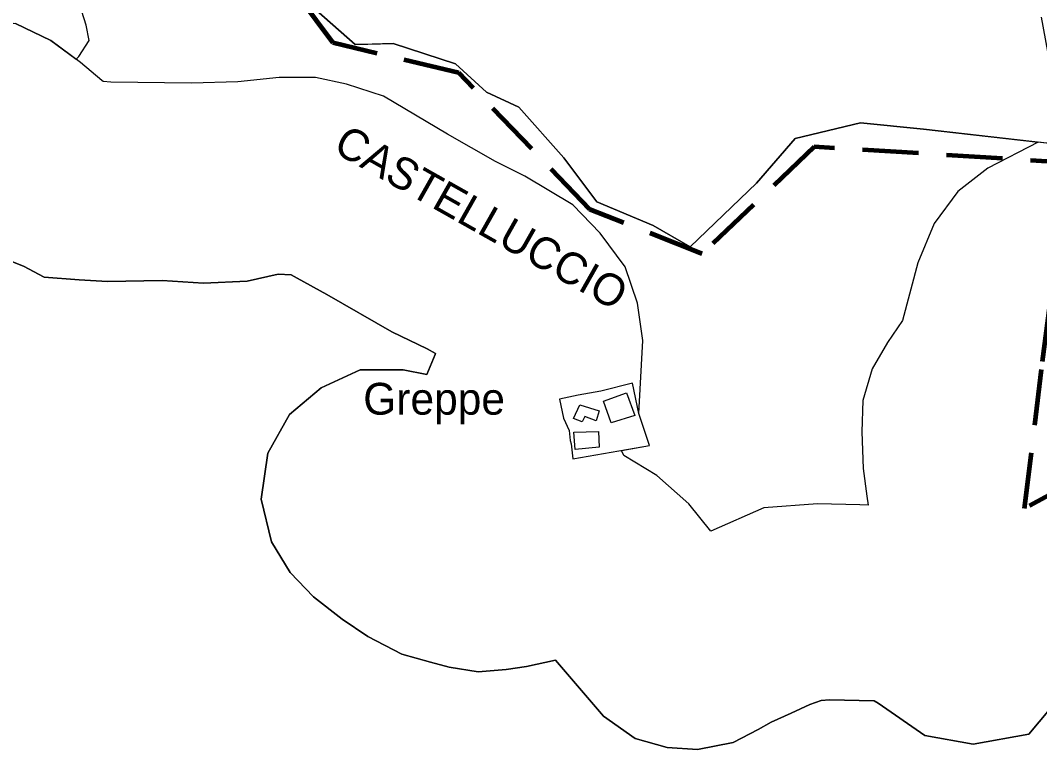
# Model space of a CAD drawing. Extents: x 645880 to 658994, y 884400 to 894744.
# Drawn here: x 657221 to 657766, y 890956 to 891347 of the extents above; entities that cross this region are included whole.
import ezdxf
from ezdxf.enums import TextEntityAlignment as Align

# ---------------------------------------------------------------- set-up
doc = ezdxf.new("R2010")
doc.units = 0
doc.header["$LTSCALE"] = 10
doc.linetypes.add('MEDIUM_DASHED', pattern=[4.5, 3, -1.5])
for name, color, linetype, lineweight in [('10', 7, 'Continuous', 25), ('15', 7, 'MEDIUM_DASHED', 100), ('16', 7, 'Continuous', 25), ('17', 7, 'Continuous', 25), ('18', 7, 'Continuous', 25), ('2', 7, 'Continuous', 25), ('55', 7, 'Continuous', 25)]:
    doc.layers.add(name, color=color, linetype=linetype, lineweight=lineweight)
doc.layers.add('60', color=7, linetype='Continuous')

msp = doc.modelspace()

# ---------------------------------------------------------------- linework, layer by layer
at = {"layer": '10'}
for points in [[(657400.09, 891334.33), (657379.16, 891352.71), (657364.34, 891378.02)], [(657767.03, 891348.96), (657770.45, 891330.62), (657796.14, 891285.04), (657790.22, 891279.18), (657704.19, 891289.09), (657670.46, 891292.46), (657635.51, 891284.06), (657614.74, 891260.2), (657579.26, 891226.05), (657559.49, 891237.53), (657529.31, 891250.16), (657511.7, 891273.75), (657487.58, 891300.87), (657470.34, 891308.9)], [(657470.34, 891308.9), (657453.84, 891324.08), (657420.34, 891334.9), (657403.53, 891334.4), (657400.09, 891334.33)]]:
    msp.add_lwpolyline(points, dxfattribs=at)
at = {"layer": '15'}
msp.add_lwpolyline([(657787.21, 890948.05), (657815.02, 890978.31), (657790.83, 891025.5), (657787.21, 891101.74), (657758.18, 891086.01), (657767.85, 891164.67), (657777.19, 891236.76), (657824.69, 891236.07), (657839.86, 891254.13), (657862.19, 891291.74), (657781.15, 891336.51), (657815.01, 891281.92), (657791.21, 891270.46), (657645.7, 891279.64), (657585.69, 891222.25), (657525.69, 891246.07), (657455.53, 891319.18), (657388.34, 891335.24), (657356.54, 891378.41)], dxfattribs=at)
at = {"layer": '16'}
for points in [[(657233.73, 891209.79), (657222.66, 891215.69), (657207.76, 891221.57), (657186.88, 891239.55), (657181.91, 891241.91)], [(657369.12, 891209.23), (657365.82, 891211.09), (657358.87, 891211.46), (657342.39, 891207.69), (657318.89, 891206.57), (657296.8, 891208.03), (657267.56, 891207.47)], [(657267.56, 891207.47), (657252.36, 891208.46), (657233.73, 891209.79)], [(657442.98, 891168.89), (657438.65, 891171.43), (657419.71, 891180.63), (657384.95, 891200.63), (657369.12, 891209.23)], [(657381.98, 891150.53), (657402.68, 891160.28), (657425.69, 891160.28), (657438.49, 891157.65), (657442.86, 891168.48), (657442.98, 891168.89)], [(657353.31, 891115.64), (657364.94, 891136.32), (657381.98, 891150.53)], [(657355.24, 891068.19), (657349.8, 891091.05), (657353.31, 891115.64)], [(657465.82, 890998.6), (657450.37, 891001.07), (657440.34, 891003.78), (657425.11, 891008.01), (657406.77, 891017.42), (657393.09, 891026.81), (657377.76, 891038.7), (657365.28, 891051.75), (657355.24, 891068.19)], [(657532.97, 890974.79), (657507.22, 891004.9), (657491.8, 891001.44), (657480.93, 890999.76), (657465.82, 890998.6)], [(657789.7, 891004.96), (657777.02, 890985.03), (657760.54, 890965.24), (657730.64, 890959.81), (657704.85, 890964.5)], [(657677.72, 890983.07), (657653.82, 890983.66), (657649.31, 890983.3), (657643.3, 890981.06), (657633.35, 890976.45)], [(657704.85, 890964.5), (657679.86, 890981.84), (657677.8, 890983.08), (657677.72, 890983.07)], [(657633.35, 890976.45), (657622.58, 890971.55), (657615.61, 890967.7), (657602.29, 890960.75), (657583.15, 890956.92), (657567, 890957.99), (657549.79, 890962.92), (657532.97, 890974.79)]]:
    msp.add_lwpolyline(points, dxfattribs=at)
at = {"layer": '17'}
for points in [[(657250.88, 891326.49), (657252.25, 891327.9), (657257.83, 891336.58), (657256.18, 891344.65), (657253.77, 891352.04), (657237.53, 891417.04), (657234.28, 891423.54), (657233.47, 891439.79)], [(656932.1, 891401.4), (656948.8, 891405.66), (656966.63, 891408.32), (656979.51, 891409.14), (656995.73, 891411.78), (657026.54, 891408.63), (657046.03, 891397.59), (657048.71, 891395.74), (657056.19, 891398.66), (657073.11, 891404.08), (657086.2, 891407.44), (657105.68, 891410.91), (657137.14, 891410.14), (657161.32, 891393.45), (657175.26, 891379.51), (657195.63, 891354.74), (657199.58, 891349.58), (657200.27, 891349.15), (657204.3, 891347.59), (657218.39, 891345.62), (657237.24, 891336.54), (657250.88, 891326.49)]]:
    msp.add_lwpolyline(points, dxfattribs=at)
at = {"layer": '18'}
for points in [[(657250.88, 891326.49), (657252.25, 891327.9), (657257.83, 891336.58), (657256.18, 891344.65), (657253.77, 891352.04), (657237.53, 891417.04), (657234.28, 891423.54), (657233.47, 891439.79)], [(657379.16, 891352.71), (657400.09, 891334.33), (657420.34, 891334.9), (657453.84, 891324.08), (657470.34, 891308.9), (657487.58, 891300.87), (657511.7, 891273.75), (657529.31, 891250.16), (657559.49, 891237.53), (657579.26, 891226.05), (657614.74, 891260.2), (657635.51, 891284.06), (657670.46, 891292.46), (657704.19, 891289.09), (657765.49, 891282.03)], [(657551.79, 891136.87), (657553.99, 891175.96), (657551.06, 891195.93), (657544.57, 891215.41), (657531.09, 891233.39), (657516.46, 891248.55), (657490.87, 891263.91), (657475.13, 891271.79), (657449.41, 891286.38), (657415.25, 891306.69), (657395.5, 891313.13), (657378.78, 891316.79), (657359.49, 891316.79), (657337.36, 891314.45), (657312.44, 891313.7), (657269.31, 891314.23), (657265.33, 891314.5), (657264.48, 891315.09), (657253.17, 891324.8), (657250.88, 891326.49)], [(657765.49, 891282.03), (657738.62, 891268.14), (657722.46, 891255.7), (657709.84, 891238.62), (657701.17, 891217.56), (657692.81, 891186.72)], [(657692.81, 891186.72), (657684.94, 891174.92), (657676.58, 891160.79), (657671.61, 891143.89), (657671.07, 891127.08), (657671.79, 891107.41), (657673.8, 891092.6), (657674.45, 891087.82), (657670.08, 891087.93), (657647.5, 891088.57), (657618.68, 891086.27), (657590.37, 891073.83), (657578.52, 891088.57), (657561.48, 891103.72), (657543.87, 891114.29), (657542.47, 891117.09)], [(657542.47, 891117.09), (657557.59, 891119.67), (657551.79, 891136.87)]]:
    msp.add_lwpolyline(points, dxfattribs=at)
at = {"layer": '2'}
for points in [[(657509.37, 891144.45), (657511.49, 891134.27), (657514.49, 891127.67), (657515.09, 891122.47), (657515.59, 891120.67), (657516.49, 891112.67), (657557.59, 891119.67), (657551.79, 891136.87), (657548.36, 891153.07), (657531.48, 891148.85), (657519.33, 891146.65)], [(657532.86, 891143.54), (657545.16, 891148), (657549.71, 891135.84), (657537, 891131.91)], [(657516.97, 891134.15), (657520.18, 891141.58), (657530.64, 891138.2), (657528.95, 891132.97), (657522.88, 891135.16), (657521.53, 891132.46)], [(657517.11, 891126.82), (657530.3, 891127.22), (657530.64, 891118.78), (657517.74, 891117.58)]]:
    msp.add_lwpolyline(points, close=True, dxfattribs=at)
at = {"layer": '55'}
for points in [[(657692.81, 891186.72), (657684.94, 891174.92), (657676.58, 891160.79), (657671.61, 891143.89), (657671.07, 891127.08), (657671.79, 891107.41), (657673.8, 891092.6), (657674.45, 891087.82), (657670.08, 891087.93), (657647.5, 891088.57), (657618.68, 891086.27), (657590.37, 891073.83), (657578.52, 891088.57), (657561.48, 891103.72), (657543.87, 891114.29), (657542.47, 891117.09), (657557.59, 891119.67), (657551.79, 891136.87), (657553.99, 891175.96), (657551.06, 891195.93), (657544.57, 891215.41), (657531.09, 891233.39), (657516.46, 891248.55), (657490.87, 891263.91), (657475.13, 891271.79), (657449.41, 891286.38), (657415.25, 891306.69), (657395.5, 891313.13), (657378.78, 891316.79), (657359.49, 891316.79), (657337.36, 891314.45), (657312.44, 891313.7), (657269.31, 891314.23), (657265.33, 891314.5), (657264.48, 891315.09), (657253.17, 891324.8), (657237.24, 891336.54), (657218.39, 891345.62)], [(656930.24, 891287.48), (656953.29, 891297.23), (656966.64, 891299.86), (656992.46, 891303.12), (657001.83, 891294.78), (657023.56, 891283.07), (657051.82, 891285.25), (657068.13, 891290.82), (657086.94, 891296.9), (657094.05, 891299.59), (657102.96, 891297.11), (657118.93, 891278.3), (657137.16, 891262.09), (657153.75, 891249.64), (657177.1, 891242.56), (657181.91, 891241.91), (657186.88, 891239.55), (657207.76, 891221.57), (657222.66, 891215.69), (657233.73, 891209.79)], [(657803.36, 891278.69), (657796.14, 891285.04), (657790.22, 891279.18), (657765.49, 891282.03), (657738.62, 891268.14), (657722.46, 891255.7), (657709.84, 891238.62), (657701.17, 891217.56), (657692.81, 891186.72)], [(657358.87, 891211.46), (657342.39, 891207.69), (657318.89, 891206.57), (657296.8, 891208.03), (657267.56, 891207.47), (657252.36, 891208.46), (657233.73, 891209.79), (657222.66, 891215.69), (657207.76, 891221.57)], [(657233.73, 891209.79), (657252.36, 891208.46), (657267.56, 891207.47), (657296.8, 891208.03), (657318.89, 891206.57), (657342.39, 891207.69), (657358.87, 891211.46)], [(657777.02, 890985.03), (657760.54, 890965.24), (657730.64, 890959.81), (657704.85, 890964.5), (657679.86, 890981.84), (657677.8, 890983.08), (657677.72, 890983.07), (657653.82, 890983.66), (657649.31, 890983.3), (657643.3, 890981.06), (657633.35, 890976.45), (657622.58, 890971.55), (657615.61, 890967.7), (657602.29, 890960.75), (657583.15, 890956.92), (657567, 890957.99), (657549.79, 890962.92), (657532.97, 890974.79), (657507.22, 891004.9), (657491.8, 891001.44), (657480.93, 890999.76), (657465.82, 890998.6), (657450.37, 891001.07), (657440.34, 891003.78), (657425.11, 891008.01), (657406.77, 891017.42), (657393.09, 891026.81), (657377.76, 891038.7), (657365.28, 891051.75), (657355.24, 891068.19), (657349.8, 891091.05), (657353.31, 891115.64), (657364.94, 891136.32), (657381.98, 891150.53), (657402.68, 891160.28), (657425.69, 891160.28), (657438.49, 891157.65), (657442.86, 891168.48), (657442.98, 891168.89), (657438.65, 891171.43), (657419.71, 891180.63), (657384.95, 891200.63), (657369.12, 891209.23), (657365.82, 891211.09), (657358.87, 891211.46)], [(657358.87, 891211.46), (657365.82, 891211.09), (657369.12, 891209.23), (657384.95, 891200.63), (657419.71, 891180.63), (657438.65, 891171.43), (657442.98, 891168.89), (657442.86, 891168.48), (657438.49, 891157.65), (657425.69, 891160.28), (657402.68, 891160.28), (657381.98, 891150.53), (657364.94, 891136.32), (657353.31, 891115.64), (657349.8, 891091.05), (657355.24, 891068.19), (657365.28, 891051.75), (657377.76, 891038.7), (657393.09, 891026.81), (657406.77, 891017.42), (657425.11, 891008.01), (657440.34, 891003.78), (657450.37, 891001.07), (657465.82, 890998.6), (657480.93, 890999.76), (657491.8, 891001.44), (657507.22, 891004.9), (657532.97, 890974.79), (657549.79, 890962.92), (657567, 890957.99), (657583.15, 890956.92), (657602.29, 890960.75), (657615.61, 890967.7), (657622.58, 890971.55), (657633.35, 890976.45), (657643.3, 890981.06), (657649.31, 890983.3), (657653.82, 890983.66), (657677.72, 890983.07), (657677.8, 890983.08)], [(657677.8, 890983.08), (657679.86, 890981.84), (657704.85, 890964.5), (657730.64, 890959.81), (657760.54, 890965.24), (657777.02, 890985.03)]]:
    msp.add_lwpolyline(points, dxfattribs=at)

# ---------------------------------------------------------------- texts
at = {"layer": '60'}
msp.add_text('CASTELLUCCIO', height=17, rotation=330.549, dxfattribs=at).set_placement((657463.46, 891234.42), align=Align.CENTER)
msp.add_text('Greppe', height=17, dxfattribs=at).set_placement((657442.32, 891136.24), align=Align.CENTER)

doc.saveas('drawing.dxf')
